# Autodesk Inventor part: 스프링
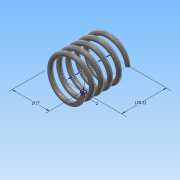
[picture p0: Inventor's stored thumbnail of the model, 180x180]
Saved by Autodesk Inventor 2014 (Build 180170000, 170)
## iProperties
Created: 2016-01
Part Number: 스프링
Material: 강철, 탄소
Document SubType Name: Modeling
Designer: Administrator
Density: 1 g/cm^3
Appearance: 반연마
Mass: 0.821689 g
Surface Area: 16.7182 cm^2
Volume: 0.821689 cm^3
Author: Administrator
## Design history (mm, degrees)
sketch "스케치1"
  geometry: L1 (0, 0)-(8.5, 0); L2 (8.5, 0)-(8.5, 20.5); L3 (8.5, 20.5)-(0, 20.5); L4 (0, 20.5)-(0, 0); C1 r 1 at (8.5, 0)
  constraints: 8 end point, 2 parallel, 1 centre point, 1 coincident, 1 horizontal, 1 perpendicular
  dimensions: "d0" = 20.5 distance of L1.end L2.end (derived); "d1" = 17 diameter of L2 L4; "d2" = 2 diameter of C1
feature "코일1" sketch "스케치1" pitch "d3" = 10; turns "d5" = 5; dims "d4" = 20.5 (= d0), "d6" = 0, angle "d7" = 90 deg, angle "d8" = 90 deg, "d9" = 0, "d10" = 0
node "작업 평면2"
  node "작업 평면1"
sketch "스케치2"
  geometry: L1 (-9.5, 0)-(-7.5, 0) reference; 1 further point
  constraints: 1 horizontal alignment
extrude "돌출1" cut sketch "스케치2" distance "d13" = 10; taper "d14" = 0 deg
sketch "스케치3"
  geometry: L1 (-7.5, 0)-(-9.5, 0) reference; 1 further point
  constraints: 1 horizontal alignment
extrude "돌출2" cut sketch "스케치3" distance "d15" = 10; taper "d16" = 0 deg
node "솔리드1"
node "절단 모서리 투영1"
node "절단 모서리 투영2"
other parameters: "d11" = 0, "d12" = 20.5 (= d0)
